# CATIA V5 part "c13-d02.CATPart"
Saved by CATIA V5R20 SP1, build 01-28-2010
Part number: Part1
Bounding box of the stored display mesh (mm): x -33 to 33, y -200.819 to 48, z -35 to 35
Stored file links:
  D:\v5_r20\psrt_files_downloaded\c13-catia-v5r20-prt\c13-catia-v5r20-figr-13-13\c13-d02.CATPart
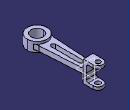
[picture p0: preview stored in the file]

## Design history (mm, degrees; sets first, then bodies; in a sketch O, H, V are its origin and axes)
Body1 (main body)
  Sketch1 on yz-plane, origin (0, 0, 0), H (0, 1, 0), V (0, 0, 1)
    line L1 (0, 0) -> (0, -35)
    point P1 (0, -35)
    line L2 (0, -35) -> (48, -35)
    point P2 (48, -35)
    line L3 (48, -35) -> (48, -25)
    point P3 (48, -25)
    line L4 (48, -25) -> (10, -25)
    point P4 (10, -25)
    line L5 (10, -25) -> (10, 0)
    point P5 (10, 0)
    point P6 (0, 0)
    point P7 (0, 0)
    point P8 (0, 35)
    point P9 (48, 35)
    point P10 (48, 25)
    point P11 (10, 25)
    point P12 (10, 0)
    point P13 (0, 0)
    line L6 (0, 0) -> (0, 35)
    line L7 (0, 35) -> (48, 35)
    line L8 (48, 35) -> (48, 25)
    line L9 (48, 25) -> (10, 25)
    line L10 (10, 25) -> (10, 0)
    length L8 = 10
    distance P3 L9 = 50
    length L2 = 48
    distance L10 L6 = 10
    vertical: L1 V, L3 V, L5 V
    horizontal: L2 H, L4 H
    symmetry: O P7 H, P1 P8 H, P2 P9 H, P3 P10 H, P4 P11 H, P5 P12 H, P6 P13 H, L1 L6 H, L2 L7 H, L3 L8 H, L4 L9 H, L5 L10 H
    coincidence: P13 P7, P12 P5, P6 P7
  Pad1: profile Sketch1, direction (1, 0, 0), length 16, mirrored extent
  Sketch2 on xy-plane, origin (0, 0, 0), H (1, 0, 0), V (0, 1, 0)
    circle A1 centre (0, -168) radius 33
    point P1 (0, -168)
    circle A2 centre (0, -168) radius 20
    distance P1 H = 168
    radius A1 = 33
    radius A2 = 20
    coincidence: P1 V
  Pad2: profile Sketch2, direction (0, 0, 1), length 16, mirrored extent
  Sketch3 on xy-plane, origin (0, 0, 0), H (1, 0, 0), V (0, 1, 0)
    line L1 (-16, 0) -> (-25, -146.4593)
    point P1 (-16, 0)
    point P2 (-25, -146.4593)
    line L2 (16, 0) -> (25, -146.4593)
    point P3 (16, 0)
    point P4 (25, -146.4593)
    reference projected line E1 (16, 48) -> (16, 0) from edge [face of Pad1 | face of Pad1]
    reference projected line E2 (-16, 48) -> (-16, 0) from edge [face of Pad1 | face of Pad1]
    projected circle E3 centre (0, -168) radius 33 from edge [face of Pad2 | face of Pad2]
    projected arc E4 centre (0, -168) radius 33 from (25, -146.4593) to (-25, -146.4593) ccw from edge [face of Pad2 | face of Pad2]
    line L3 (-16, 0) -> (16, 0)
    distance P4 P2 H = 50
    coincidence: P1 H, P3 H, P3 E1, P1 E2, P2 E3, P4 E3
    symmetry: P4 P2 V
    horizontal: L3 H
  Pad3: profile Sketch3, direction (0, 0, 1), length 8, mirrored extent
  Fillet1: radius 6, on edge [face of Pad1 | face of Pad3]; edge [face of Pad3 | face of Pad1]; edge [face of Pad1 | face of Pad1] (x2)
  Fillet2: radius 30, on edge [face of Pad3 | face of Pad2]; edge [face of Pad2 | face of Pad3]
  TritangentFillet1: Face1 face of Pad1, RemoveFace face of Pad1, Face2 face of Pad1
  TritangentFillet2: Face1 face of Pad1, RemoveFace face of Pad1, Face2 face of Pad1
  Sketch4 on face of Pad1, origin (2.8418, 32, 35), H (1, 0, 0), V (0, 1, 0)
    point P1 (-2.8418, 0)
    reference projected arc E1 centre (-2.8418, 0) radius 16 from (13.1582, 0) to (-18.8418, 0) ccw from edge [face of Pad1 | face of TritangentFillet1]
    concentricity: P1 E1
  Hole1: placed by Sketch4, at (0, 32, 35) direction (0, 0, -1), diameter 16, through (limit type 3)
  Sketch5 on face of Pad3, origin (0, 0, 8), H (1, 0, 0), V (0, 1, 0)
    construction line L1 (0, -25) -> (0, -115)
    point P1 (0, -25)
    line L2 (7, -25) -> (7, -115)
    line L3 (-7, -115) -> (-7, -25)
    arc A1 centre (0, -115) radius 7 from (7, -115) to (-7, -115) cw
    arc A2 centre (0, -25) radius 7 from (-7, -25) to (7, -25) cw
    distance P1 H = 25
    length L1 = 90
    radius A1 = 7
    coincidence: P1 V
    vertical: L1 V
    tangency: A1 L2, A2 L2, A1 L3, A2 L3
    parallelism: L1 L2
  Pocket1: profile Sketch5, direction (0, 0, -1), through (limit type 3)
